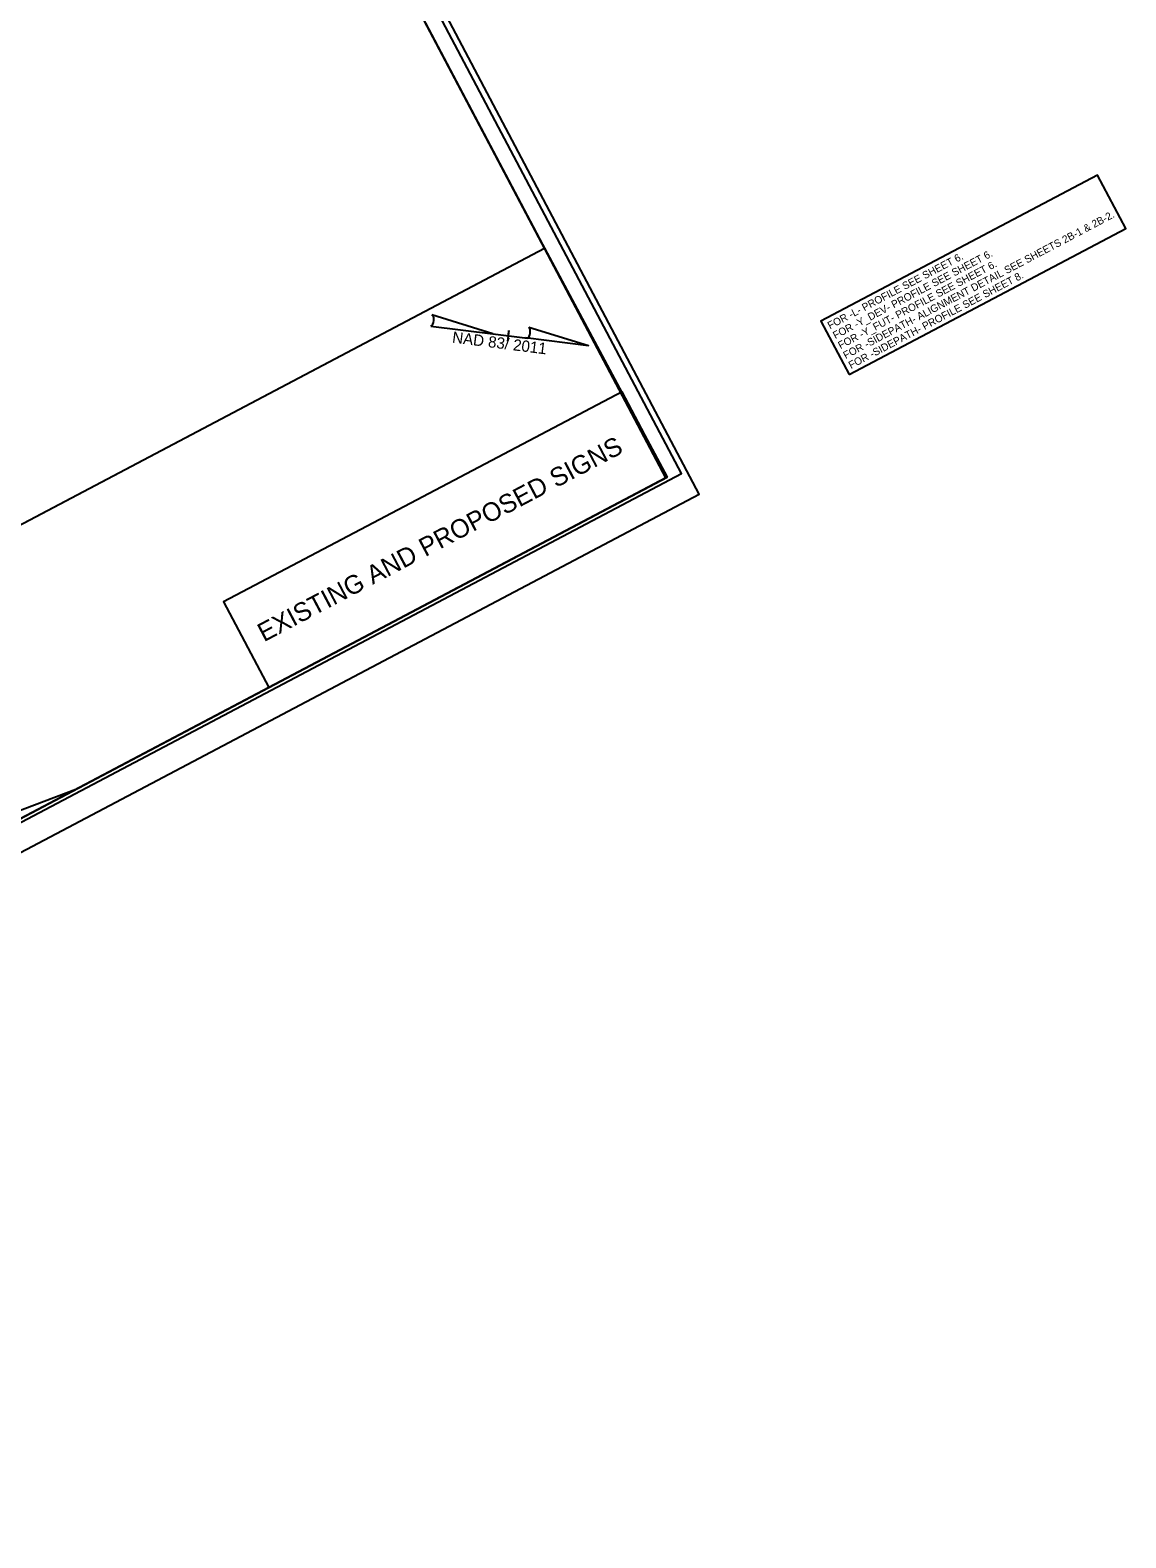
# Model space of a CAD drawing. Extents: x 1487165 to 1493546, y 497841 to 501709.
# Drawn here: x 1488839 to 1489663, y 497987 to 499122 of the extents above; entities that cross this region are included whole.
import ezdxf

# ---------------------------------------------------------------- set-up
doc = ezdxf.new("R2010")
doc.units = 0
for name, color, linetype in [('Prop Grid Mask', 7, 'Continuous'), ('Prop Horizontal Alignment Curve and Spiral Data', 7, 'Continuous'), ('Prop North Arrow NAD83 for Plan Sheets CELL', 7, 'Continuous'), ('Scratch_Level_3', 7, 'Continuous'), ('Sheet Block Title CELL', 7, 'Continuous'), ('Sheet Clip Boundary CELL', 7, 'Continuous'), ('Sheet Plot Border Inside CELL', 7, 'Continuous'), ('Sheet Plot Border Outside CELL', 7, 'Continuous'), ('Sheet Title CELL', 7, 'Continuous')]:
    doc.layers.add(name, color=color, linetype=linetype)

msp = doc.modelspace()

# ---------------------------------------------------------------- linework, layer by layer
at = {"layer": 'Prop Grid Mask'}
msp.add_lwpolyline([(1489455.1, 498863), (1489663.4, 498973), (1489642.1, 499013.2), (1489433.8, 498903.2)], close=True, dxfattribs=at)
msp.add_lwpolyline([(1489455.1, 498863), (1489663.4, 498973), (1489642.1, 499013.2), (1489433.8, 498903.2)], close=True, dxfattribs=at)
at = {"layer": 'Prop North Arrow NAD83 for Plan Sheets CELL'}
for p, q in [((1489187, 498893.8), (1489141.1, 498907.9)), ((1489140.3, 498899.6), (1489187, 498893.8)), ((1489199, 498896.2), (1489198, 498888.3)), ((1489198.6, 498892.8), (1489199, 498896.3)), ((1489199, 498896.3), (1489199, 498896.3)), ((1489214.1, 498898.7), (1489259, 498884.8)), ((1489187, 498893.8), (1489213, 498890.5)), ((1489259, 498884.7), (1489211.6, 498890.7)), ((1489211.6, 498890.7), (1489212.9, 498890.5)), ((1489259, 498884.7), (1489259, 498884.8)), ((1489259, 498884.7), (1489259, 498884.8))]:
    msp.add_line(p, q, dxfattribs=at)
for centre, start_param, end_param in [((1489140.5, 498903.7), 0.201328, 3.141593), ((1489213.1, 498894.6), 0.216388, 2.908219)]:
    msp.add_ellipse(centre, major_axis=(-0.56, -4.19), ratio=0.461098, start_param=start_param, end_param=end_param, dxfattribs=at)
at = {"layer": 'Scratch_Level_3'}
for points in [[(1487512.6, 499019.7), (1488662.1, 499625.8), (1488771.2, 499418.9), (1488936.6, 499506), (1489317.2, 498785.2), (1488242.7, 498217.8), (1488120.4, 498369.2), (1487949.5, 498194.2)], [(1489225.8, 498958.3), (1489225.8, 498958.3), (1489318.2, 498785.7), (1488873, 498550.6), (1488514.1, 498414.5), (1488536.2, 498372.8), (1488099.7, 498142.3), (1488009.2, 498316)]]:
    msp.add_lwpolyline(points, close=True, dxfattribs=at)
at = {"layer": 'Sheet Block Title CELL'}
for points in [[(1488826.9, 499713.7), (1487500.5, 499013.3), (1487990.8, 498084.8), (1489317.2, 498785.2)], [(1488008.3, 498315.4), (1489225.8, 498958.3), (1489317.2, 498785.2), (1488099.7, 498142.3)], [(1489018.3, 498627.3), (1489318.2, 498785.7), (1489284.2, 498850.1), (1488984.3, 498691.8)]]:
    msp.add_lwpolyline(points, close=True, dxfattribs=at)
at = {"layer": 'Sheet Clip Boundary CELL'}
msp.add_lwpolyline([(1487500.5, 499013.2), (1488662.1, 499625.8), (1488771.2, 499418.9), (1488936.6, 499506), (1489317.2, 498785.1), (1487990.8, 498084.7)], close=True, dxfattribs=at)
at = {"layer": 'Sheet Plot Border Inside CELL'}
msp.add_lwpolyline([(1488835.9, 499722.2), (1487363.2, 498944.6), (1487856.2, 498010.8), (1489329, 498788.5)], close=True, dxfattribs=at)
at = {"layer": 'Sheet Plot Border Outside CELL'}
msp.add_lwpolyline([(1488830.6, 499742), (1487342.4, 498956.2), (1487854.1, 497987.1), (1489342.3, 498772.9)], close=True, dxfattribs=at)

# ---------------------------------------------------------------- texts
at = {"layer": 'Prop Horizontal Alignment Curve and Spiral Data'}
for s, p in [('FOR -SIDEPATH- ALIGNMENT DETAIL SEE SHEETS 2B-1 & 2B-2.', (1489452.5, 498874.6)), ('FOR -SIDEPATH- ALIGNMENT DETAIL SEE SHEETS 2B-1 & 2B-2.', (1489452.5, 498874.6)), ('FOR -L- PROFILE SEE SHEET 6.', (1489440.7, 498897)), ('FOR -L- PROFILE SEE SHEET 6.', (1489440.7, 498897)), ('FOR -Y_DEV- PROFILE SEE SHEET 6.', (1489444.7, 498889.6)), ('FOR -Y_DEV- PROFILE SEE SHEET 6.', (1489444.7, 498889.6)), ('FOR -Y_FUT- PROFILE SEE SHEET 6.', (1489448.6, 498882.1)), ('FOR -Y_FUT- PROFILE SEE SHEET 6.', (1489448.6, 498882.1)), ('FOR -SIDEPATH- PROFILE SEE SHEET 8.', (1489456.5, 498867.2)), ('FOR -SIDEPATH- PROFILE SEE SHEET 8.', (1489456.5, 498867.2))]:
    msp.add_text(s, height=5.625, rotation=27.8351, dxfattribs=at).set_placement(p)
at = {"layer": 'Prop North Arrow NAD83 for Plan Sheets CELL'}
msp.add_text('NAD 83/ 2011', height=8.5, rotation=352.8557, dxfattribs=at).set_placement((1489156, 498887.1))
at = {"layer": 'Sheet Title CELL'}
msp.add_text('EXISTING AND PROPOSED SIGNS', height=14, rotation=27.8343, dxfattribs=at).set_placement((1489014.6, 498661.4))

doc.saveas('drawing.dxf')
